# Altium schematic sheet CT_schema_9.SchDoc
size 390 x 278 mm
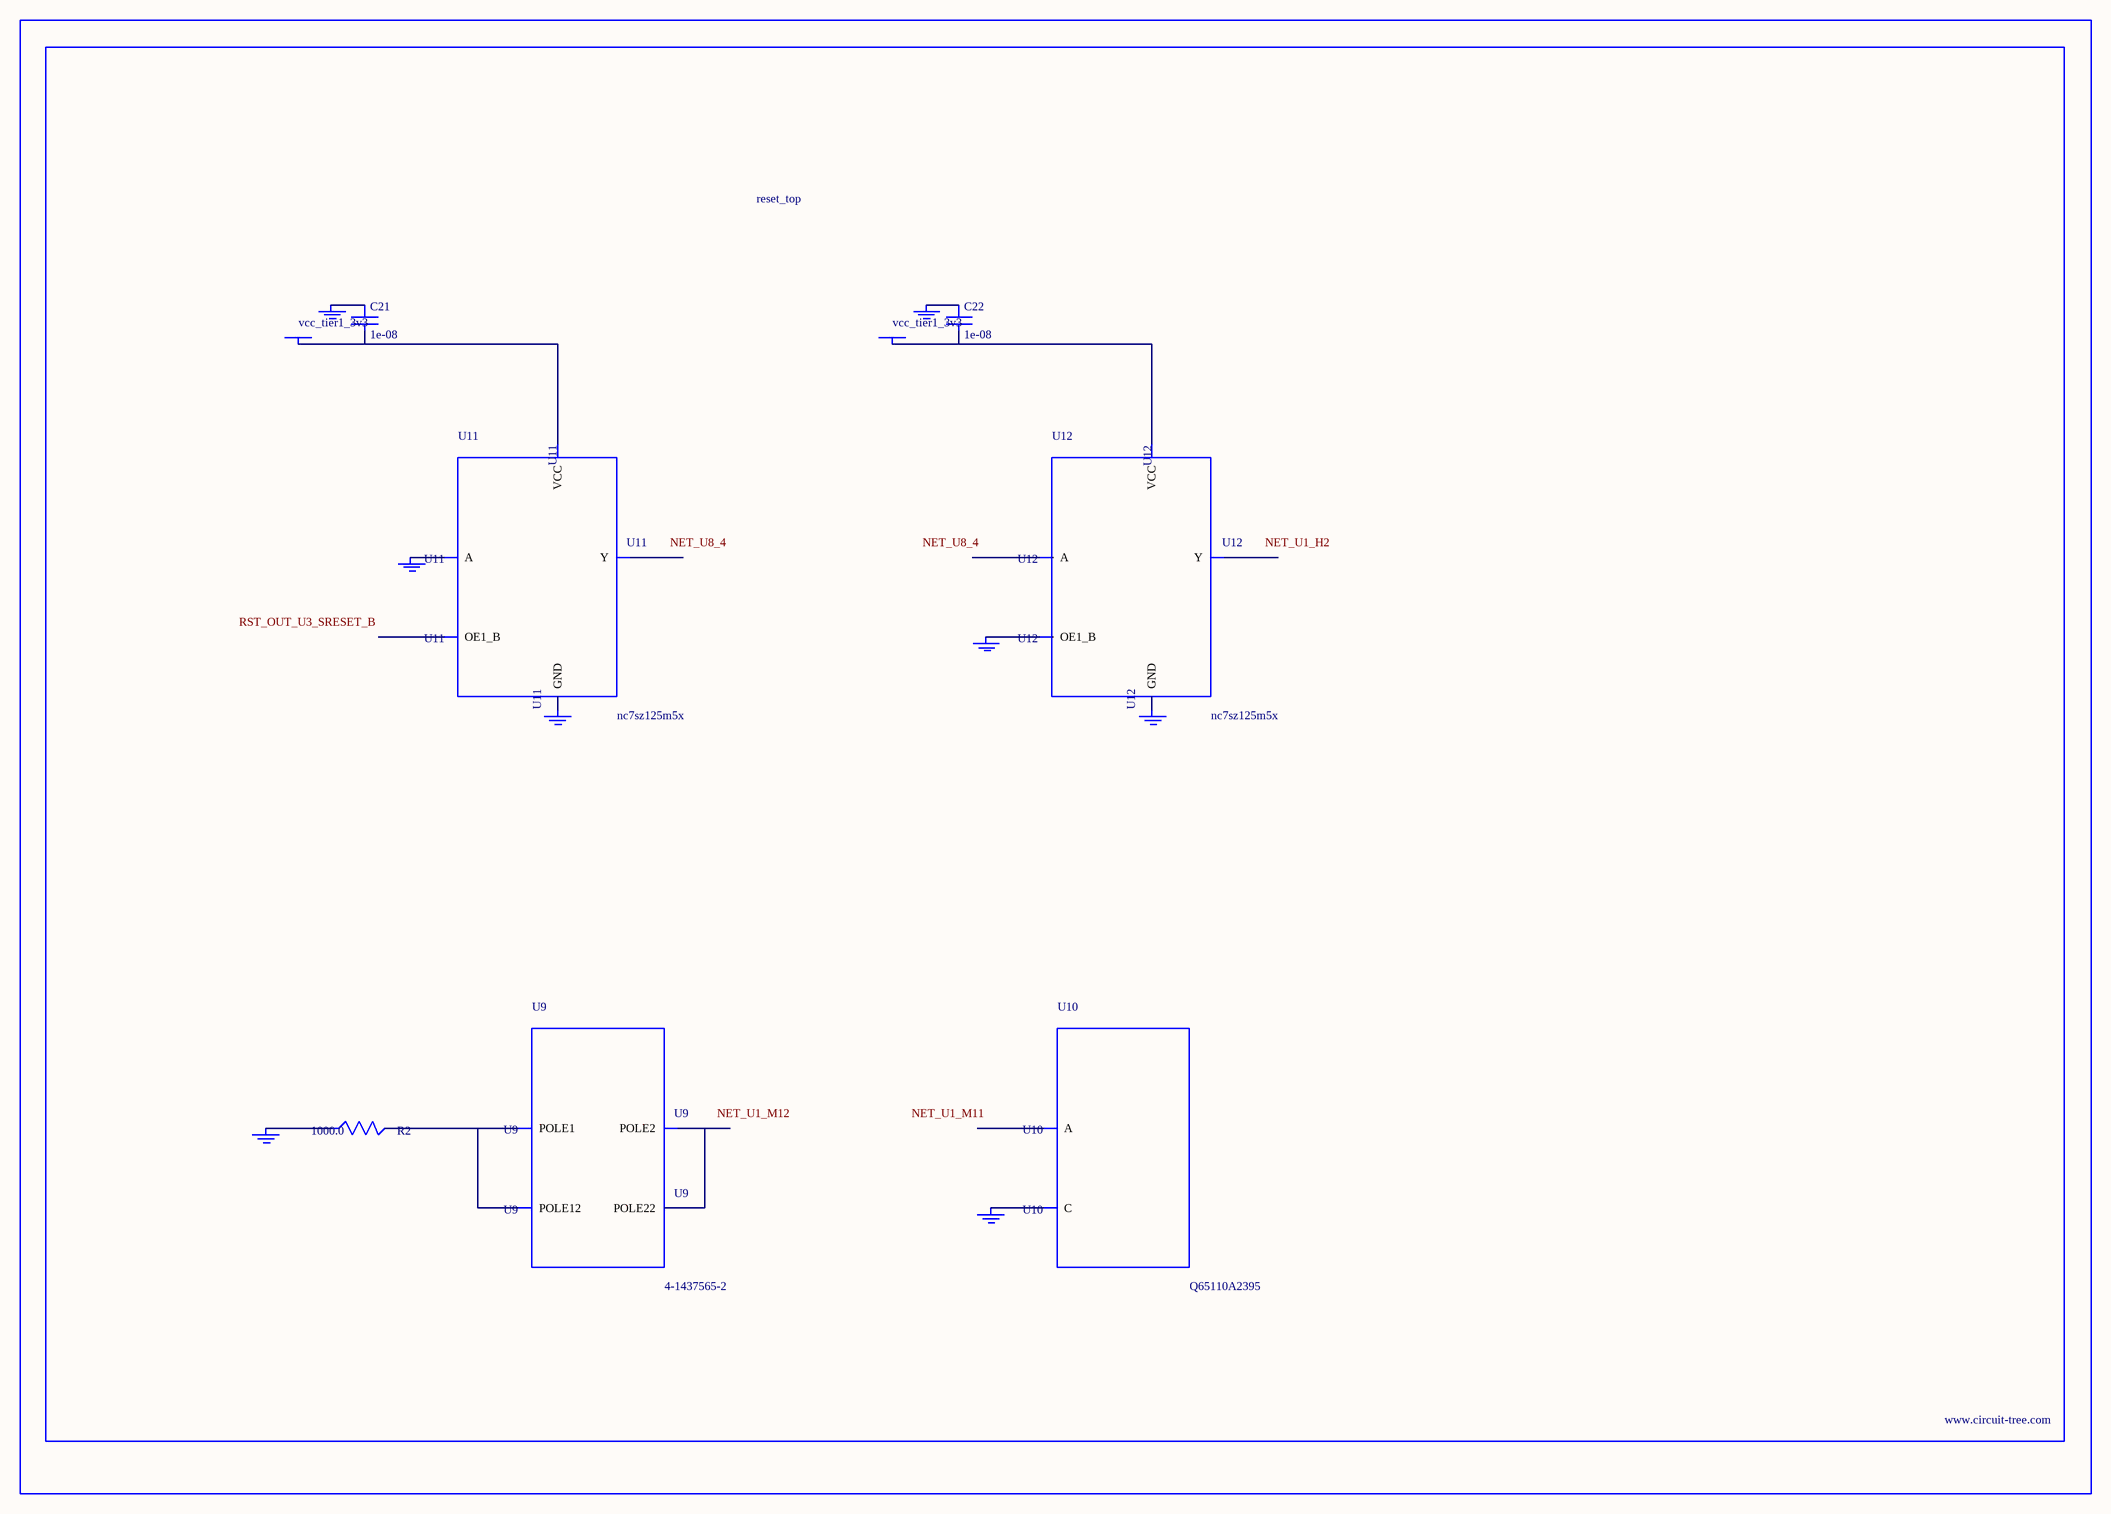
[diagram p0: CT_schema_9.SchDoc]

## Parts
BORDER8  (no value)
C21  1e-08  [C0402]
C22  1e-08  [C0402]
GND_INSTANCE_8_0  (no value)
GND_INSTANCE_8_1  (no value)
GND_INSTANCE_8_2  (no value)
GND_INSTANCE_8_3  (no value)
GND_INSTANCE_8_4  (no value)
GND_INSTANCE_8_5  (no value)
GND_INSTANCE_8_6  (no value)
GND_INSTANCE_8_7  (no value)
POWER_INSTANCE_8_0  vcc_tier1_3v3
POWER_INSTANCE_8_1  vcc_tier1_3v3
R2  1000.0  [R0603]
U9  4-1437565-2  [SW_4-1437565-2]
U10  Q65110A2395  [LGM67K-G1J2-24-Z]
U11  nc7sz125m5x  [NC7SZ125M5X]
U12  nc7sz125m5x  [NC7SZ125M5X]

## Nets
NetC21_1: C21.1 GND_INSTANCE_8_2.0(GND)
NetC21_2: C21.2 POWER_INSTANCE_8_0.0(PWR) U11.5(VCC)
NetC22_1: C22.1 GND_INSTANCE_8_5.0(GND)
NetC22_2: C22.2 POWER_INSTANCE_8_1.0(PWR) U12.5(VCC)
NetGND_INSTANCE_8_0_0: GND_INSTANCE_8_0.0(GND) R2.1
NetGND_INSTANCE_8_1_0: GND_INSTANCE_8_1.0(GND) U10.C
NetGND_INSTANCE_8_3_0: GND_INSTANCE_8_3.0(GND) U11.2(A)
NetGND_INSTANCE_8_4_0: GND_INSTANCE_8_4.0(GND) U11.3(GND)
NetGND_INSTANCE_8_6_0: GND_INSTANCE_8_6.0(GND) U12.1(OE1_B)
NetGND_INSTANCE_8_7_0: GND_INSTANCE_8_7.0(GND) U12.3(GND)
NetR2_2: R2.2 U9.1(POLE1) U9.2(POLE12)
NetU9_3: U9.3(POLE2) U9.4(POLE22)

Not connected (* = marked no-connect by the designer): U10 A; U11 1(OE1_B) 4(Y); U12 2(A) 4(Y)

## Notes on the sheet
- Labels drawn without touching a wire or pin: NET_U1_H2, NET_U1_M11, NET_U1_M12, NET_U8_4, RST_OUT_U3_SRESET_B

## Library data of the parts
BORDER8 = BORDER_PAGE8
C21 C22 = C0402C103K3RAC
GND_INSTANCE_8_0-GND_INSTANCE_8_7 = GND
POWER_INSTANCE_8_0 POWER_INSTANCE_8_1 = PWR
R2 = RC0603JR-071KL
